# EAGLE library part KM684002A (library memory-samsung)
MEMORY
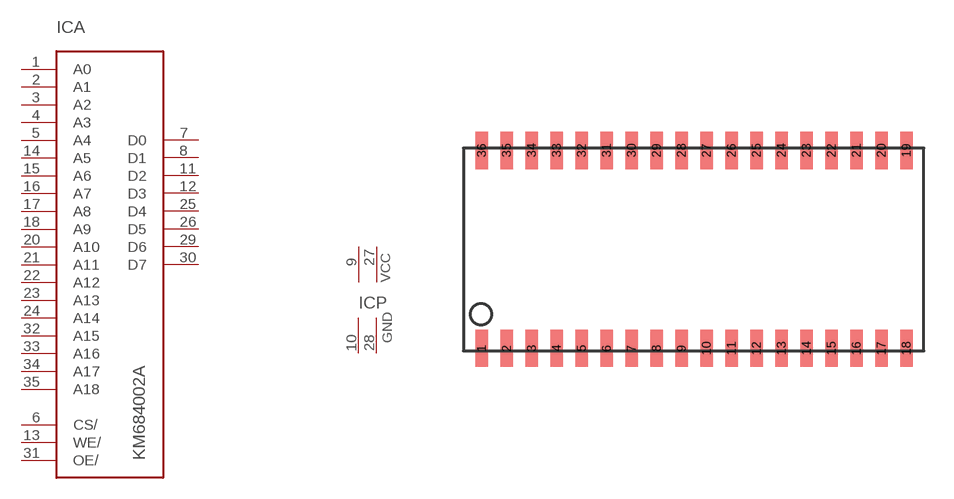
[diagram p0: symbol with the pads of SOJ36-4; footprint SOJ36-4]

Designator prefix IC; gates A=KM684002 P=P

## KM684002A (OC_FARNELL: unknown; OC_NEWARK: unknown)  [SOJ36-4]
1  A:A0  in
2  A:A1  in
3  A:A2  in
4  A:A3  in
5  A:A4  in
6  A:CS/  in
7  A:D0  hiz
8  A:D1  hiz
9  P:VCC  pwr
10  P:GND  pwr
11  A:D2  hiz
12  A:D3  hiz
13  A:WE/  in
14  A:A5  in
15  A:A6  in
16  A:A7  in
17  A:A8  in
18  A:A9  in
19  A:NC  nc
20  A:A10  in
21  A:A11  in
22  A:A12  in
23  A:A13  in
24  A:A14  in
25  A:D4  hiz
26  A:D5  hiz
27  P:VCC  pwr
28  P:GND  pwr
29  A:D6  hiz
30  A:D7  hiz
31  A:OE/  in
32  A:A15  in
33  A:A16  in
34  A:A17  in
35  A:A18  in
36  A:NC1  nc

## Footprint SOJ36-4 (pad centres in mm)
Small Outline J-Bend
smd 0.635 x 1.905: 1 -10.16,-5.029; 2 -8.89,-5.029; 3 -7.62,-5.029; 4 -6.35,-5.029; 5 -5.08,-5.029; 6 -3.81,-5.029; 7 -2.54,-5.029; 8 -1.27,-5.029; 9 0,-5.029; 10 1.27,-5.029; 11 2.54,-5.029; 12 3.81,-5.029; 13 5.08,-5.029; 14 6.35,-5.029; 15 7.62,-5.029; 16 8.89,-5.029; 17 10.16,-5.029; 18 11.43,-5.029; 19 11.43,5.029; 20 10.16,5.029; 21 8.89,5.029; 22 7.62,5.029; 23 6.35,5.029; 24 5.08,5.029; 25 3.81,5.029; 26 2.54,5.029; 27 1.27,5.029; 28 0,5.029; 29 -1.27,5.029; 30 -2.54,5.029; 31 -3.81,5.029; 32 -5.08,5.029; 33 -6.35,5.029; 34 -7.62,5.029; 35 -8.89,5.029; 36 -10.16,5.029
